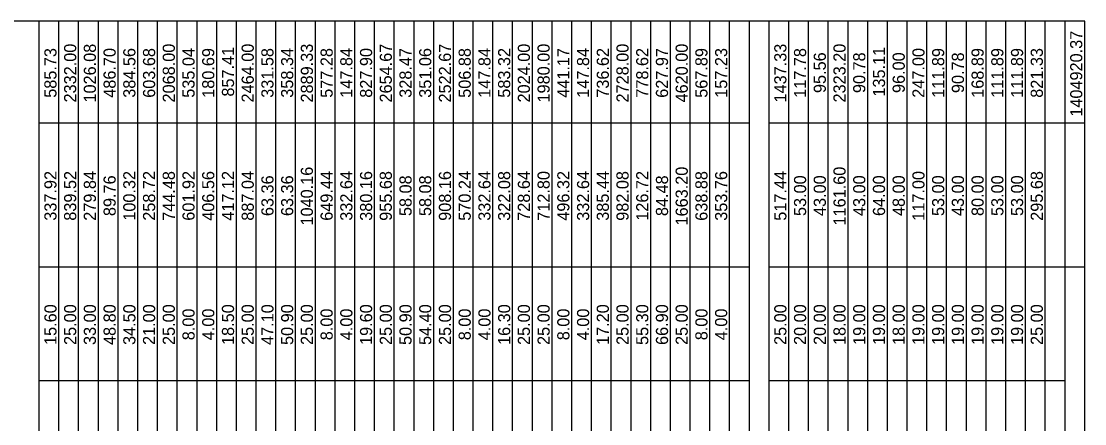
# Model space of a CAD drawing. Extents: x 2261867 to 2275370, y -3124789 to -3122260.
# Drawn here: x 2267632 to 2268157, y -3123005 to -3122807 of the extents above; entities that cross this region are included whole.
import ezdxf

# ---------------------------------------------------------------- set-up
doc = ezdxf.new("R2010")
doc.units = 0
doc.layers.add('Default', color=7, linetype='Continuous')

msp = doc.modelspace()

# ---------------------------------------------------------------- linework, layer by layer
at = {"layer": 'Default'}
for p, q in [((2268157.39, -3122806.82), (2267016.64, -3122806.82)), ((2268157.39, -3122806.82), (2267016.64, -3122806.82)), ((2267640.64, -3123394.26), (2267640.64, -3122806.82)), ((2267650.39, -3123394.26), (2267650.39, -3122806.82)), ((2267650.39, -3122857.03), (2267650.39, -3122806.82)), ((2267660.14, -3123394.26), (2267660.14, -3122806.82)), ((2267660.14, -3122857.03), (2267660.14, -3122806.82)), ((2267669.89, -3123394.26), (2267669.89, -3122806.82)), ((2267669.89, -3122857.03), (2267669.89, -3122806.82)), ((2267679.64, -3123394.26), (2267679.64, -3122806.82)), ((2267679.64, -3122857.03), (2267679.64, -3122806.82)), ((2267689.39, -3123394.26), (2267689.39, -3122806.82)), ((2267689.39, -3122857.03), (2267689.39, -3122806.82)), ((2267699.14, -3123394.26), (2267699.14, -3122806.82)), ((2267699.14, -3122857.03), (2267699.14, -3122806.82)), ((2267708.89, -3123394.26), (2267708.89, -3122806.82)), ((2267708.89, -3122857.03), (2267708.89, -3122806.82)), ((2267718.64, -3123394.26), (2267718.64, -3122806.82)), ((2267718.64, -3122857.03), (2267718.64, -3122806.82)), ((2267728.39, -3123394.26), (2267728.39, -3122806.82)), ((2267728.39, -3122857.03), (2267728.39, -3122806.82)), ((2267738.14, -3123394.26), (2267738.14, -3122806.82)), ((2267738.14, -3122857.03), (2267738.14, -3122806.82)), ((2267747.89, -3123394.26), (2267747.89, -3122806.82)), ((2267747.89, -3122857.03), (2267747.89, -3122806.82)), ((2267757.64, -3123394.26), (2267757.64, -3122806.82)), ((2267757.64, -3122857.03), (2267757.64, -3122806.82)), ((2267767.39, -3123394.26), (2267767.39, -3122806.82)), ((2267767.39, -3122857.03), (2267767.39, -3122806.82)), ((2267777.14, -3123394.26), (2267777.14, -3122806.82)), ((2267777.14, -3122857.03), (2267777.14, -3122806.82)), ((2267786.89, -3123394.26), (2267786.89, -3122806.82)), ((2267786.89, -3122857.03), (2267786.89, -3122806.82)), ((2267796.64, -3123394.26), (2267796.64, -3122806.82)), ((2267796.64, -3122857.03), (2267796.64, -3122806.82)), ((2267806.39, -3123394.26), (2267806.39, -3122806.82)), ((2267806.39, -3122857.03), (2267806.39, -3122806.82)), ((2267816.14, -3123394.26), (2267816.14, -3122806.82)), ((2267816.14, -3122857.03), (2267816.14, -3122806.82)), ((2267825.89, -3123394.26), (2267825.89, -3122806.82)), ((2267825.89, -3122857.03), (2267825.89, -3122806.82)), ((2267835.64, -3123394.26), (2267835.64, -3122806.82)), ((2267835.64, -3122857.03), (2267835.64, -3122806.82)), ((2267845.39, -3123394.26), (2267845.39, -3122806.82)), ((2267845.39, -3122857.03), (2267845.39, -3122806.82)), ((2267855.14, -3123394.26), (2267855.14, -3122806.82)), ((2267855.14, -3122857.03), (2267855.14, -3122806.82)), ((2267864.89, -3123394.26), (2267864.89, -3122806.82)), ((2267864.89, -3122857.03), (2267864.89, -3122806.82)), ((2267874.64, -3123394.26), (2267874.64, -3122806.82)), ((2267874.64, -3122857.03), (2267874.64, -3122806.82)), ((2267884.39, -3123394.26), (2267884.39, -3122806.82)), ((2267884.39, -3122857.03), (2267884.39, -3122806.82)), ((2267894.14, -3123394.26), (2267894.14, -3122806.82)), ((2267894.14, -3122857.03), (2267894.14, -3122806.82)), ((2267903.89, -3123394.26), (2267903.89, -3122806.82)), ((2267903.89, -3122857.03), (2267903.89, -3122806.82)), ((2267913.64, -3123394.26), (2267913.64, -3122806.82)), ((2267913.64, -3122857.03), (2267913.64, -3122806.82)), ((2267923.39, -3123394.26), (2267923.39, -3122806.82)), ((2267923.39, -3122857.03), (2267923.39, -3122806.82)), ((2267933.14, -3123394.26), (2267933.14, -3122806.82)), ((2267933.14, -3122857.03), (2267933.14, -3122806.82)), ((2267942.89, -3123394.26), (2267942.89, -3122806.82)), ((2267942.89, -3122857.03), (2267942.89, -3122806.82)), ((2267952.64, -3123394.26), (2267952.64, -3122806.82)), ((2267952.64, -3122857.03), (2267952.64, -3122806.82)), ((2267962.39, -3123394.26), (2267962.39, -3122806.82)), ((2267962.39, -3122857.03), (2267962.39, -3122806.82)), ((2267972.14, -3123394.26), (2267972.14, -3122806.82)), ((2267972.14, -3122857.03), (2267972.14, -3122806.82)), ((2267981.89, -3123394.26), (2267981.89, -3122806.82)), ((2267981.89, -3122857.03), (2267981.89, -3122806.82)), ((2267991.64, -3122857.03), (2267991.64, -3122806.82)), ((2267991.64, -3123394.26), (2267991.64, -3122806.82)), ((2268001.39, -3123394.26), (2268001.39, -3122806.82)), ((2268011.14, -3123394.26), (2268011.14, -3122806.82)), ((2268011.14, -3122857.03), (2268011.14, -3122806.82)), ((2268020.89, -3123394.26), (2268020.89, -3122806.82)), ((2268020.89, -3122857.03), (2268020.89, -3122806.82)), ((2268030.64, -3123394.26), (2268030.64, -3122806.82)), ((2268030.64, -3122857.03), (2268030.64, -3122806.82)), ((2268040.39, -3123394.26), (2268040.39, -3122806.82)), ((2268040.39, -3122857.03), (2268040.39, -3122806.82)), ((2268050.14, -3123394.26), (2268050.14, -3122806.82)), ((2268050.14, -3122857.03), (2268050.14, -3122806.82)), ((2268059.89, -3123394.26), (2268059.89, -3122806.82)), ((2268059.89, -3122857.03), (2268059.89, -3122806.82)), ((2268069.64, -3123394.26), (2268069.64, -3122806.82)), ((2268069.64, -3122857.03), (2268069.64, -3122806.82)), ((2268079.39, -3123394.26), (2268079.39, -3122806.82)), ((2268079.39, -3122857.03), (2268079.39, -3122806.82)), ((2268089.14, -3123394.26), (2268089.14, -3122806.82)), ((2268089.14, -3122857.03), (2268089.14, -3122806.82)), ((2268098.89, -3123394.26), (2268098.89, -3122806.82)), ((2268098.89, -3122857.03), (2268098.89, -3122806.82)), ((2268108.64, -3123394.26), (2268108.64, -3122806.82)), ((2268108.64, -3122857.03), (2268108.64, -3122806.82)), ((2268118.39, -3123394.26), (2268118.39, -3122806.82)), ((2268118.39, -3122857.03), (2268118.39, -3122806.82)), ((2268128.14, -3123394.26), (2268128.14, -3122806.82)), ((2268128.14, -3122857.03), (2268128.14, -3122806.82)), ((2268137.89, -3123394.26), (2268137.89, -3122806.82)), ((2268137.89, -3122857.03), (2268137.89, -3122806.82)), ((2268147.64, -3122857.03), (2268147.64, -3122806.82)), ((2268147.64, -3123394.26), (2268147.64, -3122806.82)), ((2268157.39, -3123394.26), (2268157.39, -3122806.82)), ((2267640.64, -3122928.21), (2267640.64, -3122857.03)), ((2267991.64, -3122857.03), (2267640.64, -3122857.03)), ((2267991.64, -3122857.03), (2267640.64, -3122857.03)), ((2267650.39, -3122928.21), (2267650.39, -3122857.03)), ((2267660.14, -3122928.21), (2267660.14, -3122857.03)), ((2267669.89, -3122928.21), (2267669.89, -3122857.03)), ((2267679.64, -3122928.21), (2267679.64, -3122857.03)), ((2267689.39, -3122928.21), (2267689.39, -3122857.03)), ((2267699.14, -3122928.21), (2267699.14, -3122857.03)), ((2267708.89, -3122928.21), (2267708.89, -3122857.03)), ((2267718.64, -3122928.21), (2267718.64, -3122857.03)), ((2267728.39, -3122928.21), (2267728.39, -3122857.03)), ((2267738.14, -3122928.21), (2267738.14, -3122857.03)), ((2267747.89, -3122928.21), (2267747.89, -3122857.03)), ((2267757.64, -3122928.21), (2267757.64, -3122857.03)), ((2267767.39, -3122928.21), (2267767.39, -3122857.03)), ((2267777.14, -3122928.21), (2267777.14, -3122857.03)), ((2267786.89, -3122928.21), (2267786.89, -3122857.03)), ((2267796.64, -3122928.21), (2267796.64, -3122857.03)), ((2267806.39, -3122928.21), (2267806.39, -3122857.03)), ((2267816.14, -3122928.21), (2267816.14, -3122857.03)), ((2267825.89, -3122928.21), (2267825.89, -3122857.03)), ((2267835.64, -3122928.21), (2267835.64, -3122857.03)), ((2267845.39, -3122928.21), (2267845.39, -3122857.03)), ((2267855.14, -3122928.21), (2267855.14, -3122857.03)), ((2267864.89, -3122928.21), (2267864.89, -3122857.03)), ((2267874.64, -3122928.21), (2267874.64, -3122857.03)), ((2267884.39, -3122928.21), (2267884.39, -3122857.03)), ((2267894.14, -3122928.21), (2267894.14, -3122857.03)), ((2267903.89, -3122928.21), (2267903.89, -3122857.03)), ((2267913.64, -3122928.21), (2267913.64, -3122857.03)), ((2267923.39, -3122984.27), (2267923.39, -3122857.03)), ((2267933.14, -3122984.27), (2267933.14, -3122857.03)), ((2267942.89, -3122984.27), (2267942.89, -3122857.03)), ((2267952.64, -3122984.27), (2267952.64, -3122857.03)), ((2267962.39, -3122984.27), (2267962.39, -3122857.03)), ((2267972.14, -3122984.27), (2267972.14, -3122857.03)), ((2267981.89, -3122984.27), (2267981.89, -3122857.03)), ((2267991.64, -3122984.27), (2267991.64, -3122857.03)), ((2268001.39, -3123293.83), (2268001.39, -3122857.03)), ((2268157.39, -3122857.03), (2268001.39, -3122857.03)), ((2268147.64, -3122857.03), (2268001.39, -3122857.03)), ((2268011.14, -3122984.27), (2268011.14, -3122857.03)), ((2268020.89, -3122984.27), (2268020.89, -3122857.03)), ((2268030.64, -3122984.27), (2268030.64, -3122857.03)), ((2268040.39, -3122984.27), (2268040.39, -3122857.03)), ((2268050.14, -3122984.27), (2268050.14, -3122857.03)), ((2268059.89, -3122984.27), (2268059.89, -3122857.03)), ((2268069.64, -3122984.27), (2268069.64, -3122857.03)), ((2268079.39, -3122984.27), (2268079.39, -3122857.03)), ((2268089.14, -3122984.27), (2268089.14, -3122857.03)), ((2268098.89, -3122984.27), (2268098.89, -3122857.03)), ((2268108.64, -3122984.27), (2268108.64, -3122857.03)), ((2268118.39, -3122984.27), (2268118.39, -3122857.03)), ((2268128.14, -3122984.27), (2268128.14, -3122857.03)), ((2268137.89, -3122984.27), (2268137.89, -3122857.03)), ((2268147.64, -3123394.26), (2268147.64, -3122857.03)), ((2267991.64, -3122928.21), (2267640.64, -3122928.21)), ((2267991.64, -3122928.21), (2267640.64, -3122928.21)), ((2268157.39, -3122928.21), (2268001.39, -3122928.21)), ((2268157.39, -3122928.21), (2268001.39, -3122928.21)), ((2267991.64, -3122984.27), (2267640.64, -3122984.27)), ((2267991.64, -3122984.27), (2267640.64, -3122984.27)), ((2267991.64, -3123394.26), (2267991.64, -3122984.27)), ((2268147.64, -3122984.27), (2268001.39, -3122984.27)), ((2268147.64, -3122984.27), (2268001.39, -3122984.27))]:
    msp.add_line(p, q, dxfattribs=at)

# ---------------------------------------------------------------- texts
for s, p in [('1404920.37', (2268156.19, -3122853.88)), ('585.73', (2267649.19, -3122844.55)), ('2332.00', (2267658.94, -3122846.87)), ('1026.08', (2267668.69, -3122846.89)), ('486.70', (2267678.44, -3122844.54)), ('384.56', (2267688.19, -3122844.55)), ('603.68', (2267697.94, -3122844.56)), ('2068.00', (2267707.69, -3122846.87)), ('535.04', (2267717.44, -3122844.54)), ('180.69', (2267727.19, -3122844.56)), ('857.41', (2267736.94, -3122843.97)), ('2464.00', (2267746.69, -3122846.87)), ('331.58', (2267756.44, -3122844.56)), ('358.34', (2267766.19, -3122844.54)), ('2889.33', (2267775.94, -3122846.88)), ('577.28', (2267785.69, -3122844.56)), ('147.84', (2267795.44, -3122844.54)), ('827.90', (2267805.19, -3122844.54)), ('2654.67', (2267814.94, -3122846.88)), ('328.47', (2267824.69, -3122844.55)), ('351.06', (2267834.44, -3122844.55)), ('2522.67', (2267844.19, -3122846.88)), ('506.88', (2267853.94, -3122844.56)), ('147.84', (2267863.69, -3122844.54)), ('583.32', (2267873.44, -3122844.52)), ('2024.00', (2267883.19, -3122846.87)), ('1980.00', (2267892.94, -3122846.87)), ('441.17', (2267902.69, -3122844.55)), ('147.84', (2267912.44, -3122844.54)), ('736.62', (2267922.19, -3122844.52)), ('2728.00', (2267931.94, -3122846.87)), ('778.62', (2267941.69, -3122844.52)), ('627.97', (2267951.44, -3122844.55)), ('4620.00', (2267961.19, -3122846.87)), ('567.89', (2267970.94, -3122844.56)), ('157.23', (2267980.69, -3122844.55)), ('1437.33', (2268009.94, -3122846.88)), ('117.78', (2268019.69, -3122844.56)), ('2323.20', (2268039.19, -3122846.87)), ('135.11', (2268058.69, -3122843.97)), ('247.00', (2268078.19, -3122844.54)), ('111.89', (2268087.94, -3122844.56)), ('168.89', (2268107.44, -3122844.56)), ('111.89', (2268117.19, -3122844.56)), ('111.89', (2268126.94, -3122844.56)), ('821.33', (2268136.69, -3122844.55)), ('95.56', (2268029.44, -3122842.22)), ('90.78', (2268048.94, -3122842.23)), ('96.00', (2268068.44, -3122842.21)), ('90.78', (2268097.69, -3122842.23)), ('1040.16', (2267775.94, -3122907.58)), ('1663.20', (2267961.19, -3122907.56)), ('1161.60', (2268039.19, -3122907.56)), ('337.92', (2267649.19, -3122905.21)), ('839.52', (2267658.94, -3122905.21)), ('279.84', (2267668.69, -3122905.23)), ('89.76', (2267678.44, -3122902.92)), ('100.32', (2267688.19, -3122905.21)), ('258.72', (2267697.94, -3122905.21)), ('744.48', (2267707.69, -3122905.25)), ('601.92', (2267717.44, -3122905.21)), ('406.56', (2267727.19, -3122905.25)), ('417.12', (2267736.94, -3122905.21)), ('887.04', (2267746.69, -3122905.23)), ('63.36', (2267756.44, -3122902.92)), ('63.36', (2267766.19, -3122902.92)), ('649.44', (2267785.69, -3122905.23)), ('332.64', (2267795.44, -3122905.23)), ('380.16', (2267805.19, -3122905.25)), ('955.68', (2267814.94, -3122905.25)), ('58.08', (2267824.69, -3122902.92)), ('58.08', (2267834.44, -3122902.92)), ('908.16', (2267844.19, -3122905.25)), ('570.24', (2267853.94, -3122905.23)), ('332.64', (2267863.69, -3122905.23)), ('322.08', (2267873.44, -3122905.25)), ('728.64', (2267883.19, -3122905.23)), ('712.80', (2267892.94, -3122905.23)), ('496.32', (2267902.69, -3122905.21)), ('332.64', (2267912.44, -3122905.23)), ('385.44', (2267922.19, -3122905.23)), ('982.08', (2267931.94, -3122905.25)), ('126.72', (2267941.69, -3122905.21)), ('84.48', (2267951.44, -3122902.92)), ('638.88', (2267970.94, -3122905.25)), ('353.76', (2267980.69, -3122905.25)), ('517.44', (2268009.94, -3122905.23)), ('53.00', (2268019.69, -3122902.9)), ('43.00', (2268029.44, -3122902.9)), ('43.00', (2268048.94, -3122902.9)), ('64.00', (2268058.69, -3122902.9)), ('48.00', (2268068.44, -3122902.9)), ('117.00', (2268078.19, -3122905.23)), ('53.00', (2268087.94, -3122902.9)), ('43.00', (2268097.69, -3122902.9)), ('80.00', (2268107.44, -3122902.9)), ('53.00', (2268117.19, -3122902.9)), ('53.00', (2268126.94, -3122902.9)), ('295.68', (2268136.69, -3122905.25)), ('15.60', (2267649.19, -3122966.52)), ('25.00', (2267658.94, -3122966.52)), ('33.00', (2267668.69, -3122966.52)), ('48.80', (2267678.44, -3122966.52)), ('34.50', (2267688.19, -3122966.52)), ('21.00', (2267697.94, -3122966.52)), ('25.00', (2267707.69, -3122966.52)), ('18.50', (2267736.94, -3122966.52)), ('25.00', (2267746.69, -3122966.52)), ('47.10', (2267756.44, -3122966.52)), ('50.90', (2267766.19, -3122966.52)), ('25.00', (2267775.94, -3122966.52)), ('19.60', (2267805.19, -3122966.52)), ('25.00', (2267814.94, -3122966.52)), ('50.90', (2267824.69, -3122966.52)), ('54.40', (2267834.44, -3122966.52)), ('25.00', (2267844.19, -3122966.52)), ('16.30', (2267873.44, -3122966.52)), ('25.00', (2267883.19, -3122966.52)), ('25.00', (2267892.94, -3122966.52)), ('17.20', (2267922.19, -3122966.52)), ('25.00', (2267931.94, -3122966.52)), ('55.30', (2267941.69, -3122966.52)), ('66.90', (2267951.44, -3122966.52)), ('25.00', (2267961.19, -3122966.52)), ('25.00', (2268009.94, -3122966.52)), ('20.00', (2268019.69, -3122966.52)), ('20.00', (2268029.44, -3122966.52)), ('18.00', (2268039.19, -3122966.52)), ('19.00', (2268048.94, -3122966.52)), ('19.00', (2268058.69, -3122966.52)), ('18.00', (2268068.44, -3122966.52)), ('19.00', (2268078.19, -3122966.52)), ('19.00', (2268087.94, -3122966.52)), ('19.00', (2268097.69, -3122966.52)), ('19.00', (2268107.44, -3122966.52)), ('19.00', (2268117.19, -3122966.52)), ('19.00', (2268126.94, -3122966.52)), ('25.00', (2268136.69, -3122966.52)), ('8.00', (2267717.44, -3122964.19)), ('4.00', (2267727.19, -3122964.19)), ('8.00', (2267785.69, -3122964.19)), ('4.00', (2267795.44, -3122964.19)), ('8.00', (2267853.94, -3122964.19)), ('4.00', (2267863.69, -3122964.19)), ('8.00', (2267902.69, -3122964.19)), ('4.00', (2267912.44, -3122964.19)), ('8.00', (2267970.94, -3122964.19)), ('4.00', (2267980.69, -3122964.19))]:
    msp.add_text(s, height=6, rotation=90, dxfattribs=at).set_placement(p)

doc.saveas('drawing.dxf')
